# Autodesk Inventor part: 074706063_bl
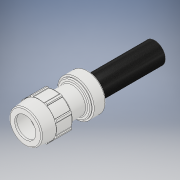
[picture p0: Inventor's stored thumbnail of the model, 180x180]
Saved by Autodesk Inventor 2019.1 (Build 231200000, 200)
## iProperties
Created: 2022-07
Part Number: 074706063_bl
Material: PVC-Piping
Description: Plasson Adjustable Elbow 63 x 63 mm
Document SubType Name: Modeling
Designer: comp2
Density: 1.4 g/cm^3
Appearance: Smooth - White
Author: comp2
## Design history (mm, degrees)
derived "07470.ipt"
feature "Solid1::07470.ipt" dims "ScaleForDerivedMember" = 10
feature "Solid2::07470.ipt" dims "ScaleForDerivedMember" = 10
feature "Solid3::07470.ipt" dims "ScaleForDerivedMember" = 10
feature "Solid4::07470.ipt" dims "ScaleForDerivedMember" = 10
tag "TaggingFeature1"
body "Solid1"
body "Solid2"
body "Solid3"
body "Solid4"
other parameters: "d0" = 384 [user parameter], "d2" = 63 [user parameter], "d6" = 113 [user parameter], "d7" = 51.66 [user parameter], "d8" = 63 [user parameter], "d9" = 45 deg [user parameter], "d10" = 31.5 [user parameter], "d11" = 195 [user parameter], "d12" = 69.3 [user parameter], "d13" = 243.75 [user parameter], "d14" = 97.5 [user parameter], "d15" = 1 [user parameter], "d16" = 35.1 [user parameter], "d17" = 91.35 [user parameter], "d19" = 103.95 [user parameter], "d20" = 8 deg [user parameter], "d21" = 39.55 [user parameter], "d22" = 6.3 [user parameter], "d24" = 8.5625 [user parameter], "d25" = 1.92 [user parameter], "d26" = 1.92 [user parameter], "d27" = 85 deg [user parameter], "d28" = 113 [user parameter], "d30" = 45.2 [user parameter], "d31" = 2 [user parameter], "d32" = 53.55 [user parameter], "d33" = 4.52 [user parameter], "d38" = 105.09 [user parameter], "d39" = 35 deg [user parameter], "d40" = 17.5 deg [user parameter], "d42" = 0 [user parameter], "d43" = 2.26 [user parameter], "d47" = 360 deg [user parameter], "d49" = 3.15 [user parameter], "d50" = 10.17 [user parameter], "l1" = 195 [user parameter], "l_" = 113 [user parameter], "H_" = 384 [user parameter], "E_" = 113 [user parameter], "d" = 63 [user parameter], "d1" = 63 [user parameter], "d23" = 8.5625 [user parameter]
